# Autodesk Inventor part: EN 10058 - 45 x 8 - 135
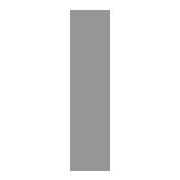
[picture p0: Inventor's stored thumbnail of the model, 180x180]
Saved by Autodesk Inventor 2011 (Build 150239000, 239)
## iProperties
_CCFamilyMember: 49
_CCFamilyDisplayName: DIN EN 10058 - Hot rolled flat steel bars for general purposes
_FrameMemberDoc: Frame Member File
_Version: 15.0.0
_GetPNFromCC: 1
Created: 2010-02
Part Number: EN 10058 - 45 x 8 - 135
Material: Steel, A36
Description: flat steel bar 45*8
Document SubType Name: Modeling
Standard: DIN
Designer: PC
Standard Revision: 2004
Standards Organization: DIN
Language: en-US
Size Designation: 45 x 8
Categories: <MemberInstance><Categories><Category DisplayName="Structural Shapes" InternalName="089c4875-fa83-4c05-b084-43b9cc11f5ed" Mnemonic="GRDR"><CategoryParameter Dis
Stock Number: 45 x 8
Density: 7.85 g/cm^3
IsCustomPart: 1
G_L: 135.000 mm
G_W: 8.000 mm
G_H: 45.000 mm
+925762B7-97C9-4CD2-B844-D50B71935541+CUTDETAIL1: Cut
Author: PC
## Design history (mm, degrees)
node "Start plane"
node "End plane"
sketch "Sketch"
  geometry: L1 (4, -22.5)-(-4, -22.5); L2 (-4, -22.5)-(-4, 22.5); L3 (-4, 22.5)-(4, 22.5); L4 (4, 22.5)-(4, -22.5); L5 (-6, 0)-(8, 0); L6 (0, -30)-(0, 40); L7 (0, 54)-(0, -44) reference; L8 (-9.2, 0)-(13.2, 0) reference
  constraints: 12 end point, 2 collinear, 2 parallel, 1 horizontal, 1 perpendicular
  dimensions: "d0" = 45 distance between parallel lines of L3 L1 (= G_W); "d1" = 8 distance between parallel lines of L4 L2 (= G_H); "d4" = 4 distance between parallel lines of L6 L4 (= 0.5 x d1); "d5" = 22.5 distance between parallel lines of L5 L3 (= 0.5 x d0)
extrude "Body" new body sketch "Sketch" stored distance "d2" = 135 (= G_L); taper "d3" = 0 deg
node "Driven Length"
  sketch "Sketch3"
    geometry: L1 (0, 0)-(10, 0) reference
    constraints: 2 end point, 1 horizontal
  workplane "Work Plane3"
  sketch "Sketch4"
    geometry: L1 (-2, 0)-(12, 0) reference; L2 (-2, 135)-(12, 135) reference
    dimensions: "d9" = 135 distance between parallel lines of L1 L2 (derived)
workplane "Work Plane4"
split "Split1"
body "Solid1"
other parameters: "G_W" = 45 [user parameter; used in 1 equation term], "G_H" = 8 [user parameter; used in 1 equation term], "G_L" = 135 (= d9) [user parameter; used in 1 equation term], "G_OFFSET_START" = 0 [user parameter; used in 1 equation term], "G_OFFSET_END" = 45 [user parameter; used in 1 equation term], "d6" = 0 (computed from G_OFFSET_START), "d7" = 135 (= G_OFFSET_END + B_L), "d8" = 90 deg, "MAS" = 0.283 [user parameter]
